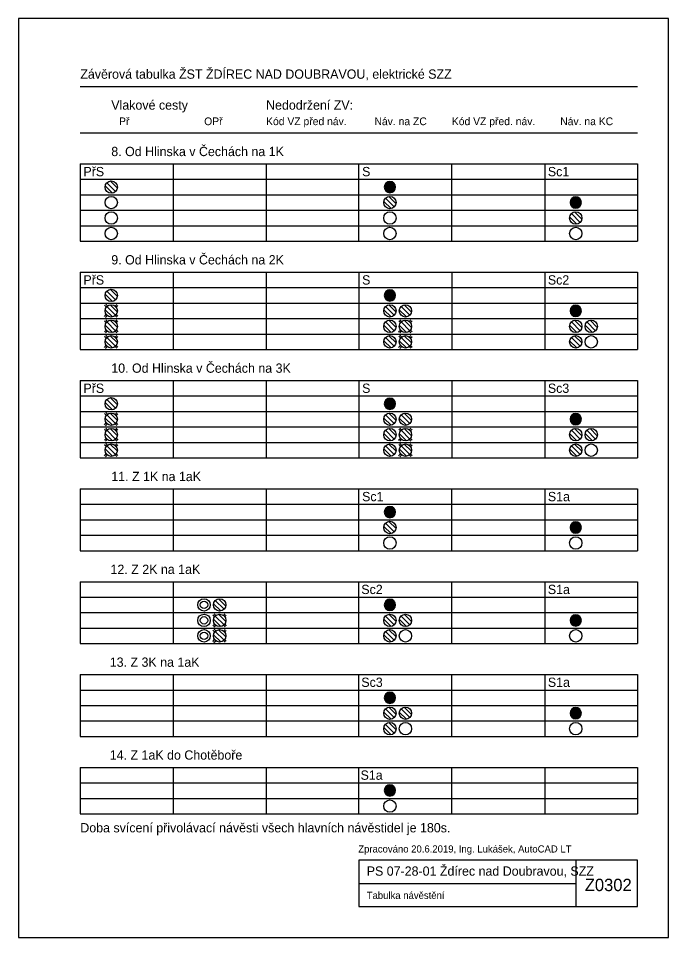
# Model space of a CAD drawing. Extents: x 2343 to 5155, y -3940 to 2050.
# Drawn here: x 4130 to 4340, y -3940 to -3643 of the extents above; entities that cross this region are included whole.
import ezdxf

# ---------------------------------------------------------------- set-up
doc = ezdxf.new("R2010")
doc.units = 0
for name, color, linetype in [('0B', 7, 'Continuous'), ('Implicitní', 7, 'Continuous'), ('Vrstva 63', 7, 'Continuous')]:
    doc.layers.add(name, color=color, linetype=linetype)

# ---------------------------------------------------------------- blocks, each defined once
blk = doc.blocks.new('ZT75')
at = {"layer": 'Implicitní'}
for points in [[(-18.1, 3.2), (18.1, 3.2)], [(-17.6, 0.7), (17.6, 0.7)], [(-17.3, 6.4), (17.3, 6.4)], [(-15.7, 9.6), (15.7, 9.6)], [(-14, 12), (14, 12)], [(-12.4, 13.6), (12.4, 13.6)], [(-10.4, 15.2), (10.4, 15.2)], [(-7.6, 16.8), (7.6, 16.8)], [(-18.1, -3.2), (18.1, -3.2)], [(-17.6, -0.7), (17.6, -0.7)], [(-17.3, -6.4), (17.3, -6.4)], [(-15.7, -9.6), (15.7, -9.6)], [(-14, -12), (14, -12)], [(-12.4, -13.6), (12.4, -13.6)], [(-10.4, -15.2), (10.4, -15.2)], [(-7.6, -16.8), (7.6, -16.8)]]:
    blk.add_lwpolyline(points, dxfattribs=at)
for start, end in [(0, 180), (180, 0)]:
    blk.add_arc((0, 0), 18.4, start, end, dxfattribs=at)
blk = doc.blocks.new('ZT76')
at = {"layer": 'Implicitní'}
for p, q in [((3.7, 19.7), (-19.7, -3.7)), ((14.1, 14.1), (-14.1, -14.1)), ((19.7, 3.7), (-3.7, -19.7))]:
    blk.add_line(p, q, dxfattribs=at)
blk.add_circle((0, 0), 20, dxfattribs=at)
blk = doc.blocks.new('ZT74')
at = {"layer": 'Implicitní'}
blk.add_circle((0, 0), 20, dxfattribs=at)
blk = doc.blocks.new('ZT78')
at = {"layer": 'Implicitní'}
for p, q in [((-30.7, 25.7), (-22.7, 17.7)), ((-25.7, 30.7), (-17.7, 22.7)), ((17.5, 21.7), (25.5, 29.7)), ((22.5, 16.7), (30.5, 24.7)), ((-31.3, -25.5), (-23.3, -17.5)), ((-26.3, -30.5), (-18.3, -22.5)), ((17.5, -21.7), (25.5, -29.7)), ((22.5, -16.7), (30.5, -24.7))]:
    blk.add_line(p, q, dxfattribs=at)
blk = doc.blocks.new('ZT72')
at = {"layer": 'Implicitní'}
for radius in [20, 12]:
    blk.add_circle((0, 0), radius, dxfattribs=at)

msp = doc.modelspace()

# ---------------------------------------------------------------- linework, layer by layer
at = {"layer": '0B'}
for p, q in [((4150, -3665), (4330, -3665)), ((4150, -3680), (4330, -3680)), ((4150, -3690), (4330, -3690)), ((4150, -3690), (4150, -3715)), ((4180, -3690), (4180, -3715)), ((4210, -3690), (4210, -3715)), ((4240, -3715), (4240, -3690)), ((4270, -3715), (4270, -3690)), ((4300, -3690), (4300, -3715)), ((4330, -3690), (4330, -3715)), ((4150, -3695), (4330, -3695)), ((4150, -3700), (4330, -3700)), ((4150, -3705), (4330, -3705)), ((4150, -3705), (4330, -3705)), ((4150, -3710), (4330, -3710)), ((4150, -3715), (4330, -3715)), ((4150, -3725), (4330, -3725)), ((4150, -3725), (4150, -3750)), ((4180, -3725), (4180, -3750)), ((4210, -3725), (4210, -3750)), ((4240, -3725), (4240, -3750)), ((4270, -3725), (4270, -3750)), ((4300, -3725), (4300, -3750)), ((4330, -3725), (4330, -3750)), ((4150, -3730), (4330, -3730)), ((4150, -3730), (4330, -3730)), ((4150, -3735), (4330, -3735)), ((4150, -3740), (4330, -3740)), ((4150, -3740), (4330, -3740)), ((4150, -3745), (4330, -3745)), ((4150, -3745), (4330, -3745)), ((4150, -3745), (4330, -3745)), ((4150, -3750), (4330, -3750)), ((4150, -3760), (4330, -3760)), ((4150, -3760), (4150, -3785)), ((4180, -3760), (4180, -3785)), ((4210, -3760), (4210, -3785)), ((4240, -3760), (4240, -3785)), ((4270, -3760), (4270, -3785)), ((4300, -3760), (4300, -3785)), ((4330, -3760), (4330, -3785)), ((4150, -3765), (4330, -3765)), ((4150, -3765), (4330, -3765)), ((4150, -3770), (4330, -3770)), ((4150, -3775), (4330, -3775)), ((4150, -3775), (4330, -3775)), ((4150, -3780), (4330, -3780)), ((4150, -3780), (4330, -3780)), ((4150, -3780), (4330, -3780)), ((4150, -3785), (4330, -3785)), ((4150, -3795), (4330, -3795)), ((4150, -3795), (4150, -3815)), ((4180, -3795), (4180, -3815)), ((4210, -3795), (4210, -3815)), ((4240, -3815), (4240, -3795)), ((4270, -3815), (4270, -3795)), ((4300, -3795), (4300, -3815)), ((4330, -3795), (4330, -3815)), ((4150, -3800), (4330, -3800)), ((4150, -3805), (4330, -3805)), ((4150, -3810), (4330, -3810)), ((4150, -3810), (4330, -3810)), ((4150, -3815), (4330, -3815)), ((4150, -3825), (4330, -3825)), ((4150, -3825), (4150, -3845)), ((4180, -3825), (4180, -3845)), ((4210, -3825), (4210, -3845)), ((4240, -3845), (4240, -3825)), ((4270, -3845), (4270, -3825)), ((4300, -3825), (4300, -3845)), ((4330, -3825), (4330, -3845)), ((4150, -3830), (4330, -3830)), ((4150, -3835), (4330, -3835)), ((4150, -3840), (4330, -3840)), ((4150, -3840), (4330, -3840)), ((4150, -3845), (4330, -3845)), ((4150, -3855), (4330, -3855)), ((4150, -3855), (4150, -3875)), ((4180, -3855), (4180, -3875)), ((4210, -3855), (4210, -3875)), ((4240, -3875), (4240, -3855)), ((4270, -3875), (4270, -3855)), ((4300, -3855), (4300, -3875)), ((4330, -3855), (4330, -3875)), ((4150, -3860), (4330, -3860)), ((4150, -3865), (4330, -3865)), ((4150, -3870), (4330, -3870)), ((4150, -3870), (4330, -3870)), ((4150, -3875), (4330, -3875)), ((4150, -3885), (4330, -3885)), ((4150, -3885), (4150, -3900)), ((4180, -3885), (4180, -3900)), ((4210, -3885), (4210, -3900)), ((4240, -3900), (4240, -3885)), ((4270, -3900), (4270, -3885)), ((4300, -3885), (4300, -3900)), ((4330, -3885), (4330, -3900)), ((4150, -3890), (4330, -3890)), ((4150, -3895), (4330, -3895)), ((4150, -3900), (4330, -3900)), ((4150, -3900), (4330, -3900)), ((4330, -3915), (4240, -3915)), ((4240, -3915), (4240, -3930)), ((4310, -3915), (4310, -3930)), ((4330, -3930), (4330, -3915)), ((4240, -3922.5), (4310, -3922.5)), ((4240, -3930), (4330, -3930))]:
    msp.add_line(p, q, dxfattribs=at)
at = {"layer": 'Vrstva 63'}
msp.add_lwpolyline([(4130, -3940), (4340, -3940), (4340, -3643), (4130, -3643)], close=True, dxfattribs=at)

# ---------------------------------------------------------------- block references
at = {"xscale": 0.1, "yscale": 0.10000000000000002}
for p in [(4189.95, -3832.5), (4189.95, -3837.5), (4189.95, -3842.5)]:
    msp.add_blockref('ZT72', p, dxfattribs=at)
at = {"layer": '0B'}
for name, p, xscale, yscale, rotation in [('ZT76', (4160, -3697.5), 0.10000000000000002, 0.1, 89.99999999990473), ('ZT75', (4250, -3697.5), 0.1, 0.10000000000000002, -9.526953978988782e-11), ('ZT74', (4160, -3702.5), 0.1, 0.10000000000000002, -9.526953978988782e-11), ('ZT76', (4250, -3702.5), 0.10000000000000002, 0.1, 89.99999999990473), ('ZT75', (4310, -3702.5), 0.1, 0.10000000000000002, -9.526953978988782e-11), ('ZT74', (4160, -3707.5), 0.1, 0.10000000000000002, -9.526953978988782e-11), ('ZT74', (4250, -3707.5), 0.1, 0.10000000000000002, -9.526953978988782e-11), ('ZT76', (4310, -3707.5), 0.10000000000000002, 0.10000000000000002, 89.99999999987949), ('ZT74', (4160, -3712.5), 0.1, 0.10000000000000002, -9.526953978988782e-11), ('ZT74', (4250, -3712.5), 0.1, 0.10000000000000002, -9.526953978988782e-11), ('ZT74', (4310, -3712.5), 0.1, 0.10000000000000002, -9.526953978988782e-11), ('ZT76', (4160, -3732.5), 0.10000000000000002, 0.10000000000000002, 89.99999999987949), ('ZT75', (4250, -3732.5), 0.1, 0.10000000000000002, -1.2050326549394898e-10), ('ZT78', (4160, -3737.5), 0.06999999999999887, 0.06999999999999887, -1.2050326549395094e-10), ('ZT76', (4160, -3737.5), 0.10000000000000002, 0.10000000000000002, 89.99999999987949), ('ZT76', (4250, -3737.5), 0.10000000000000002, 0.10000000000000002, 89.99999999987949), ('ZT76', (4255, -3737.5), 0.10000000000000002, 0.10000000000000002, 89.99999999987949), ('ZT76', (4255, -3737.5), 0.10000000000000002, 0.10000000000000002, 89.99999999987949), ('ZT75', (4310, -3737.5), 0.1, 0.10000000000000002, -1.2050326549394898e-10), ('ZT78', (4160, -3742.5), 0.06999999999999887, 0.06999999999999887, -1.2050326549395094e-10), ('ZT76', (4160, -3742.5), 0.10000000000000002, 0.10000000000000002, 89.99999999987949), ('ZT76', (4250, -3742.5), 0.10000000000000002, 0.10000000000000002, 89.99999999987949), ('ZT78', (4255, -3742.5), 0.06999999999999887, 0.06999999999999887, -1.2050326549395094e-10), ('ZT76', (4255, -3742.5), 0.10000000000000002, 0.10000000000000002, 89.99999999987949), ('ZT76', (4255, -3742.5), 0.10000000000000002, 0.10000000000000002, 89.99999999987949), ('ZT76', (4310, -3742.5), 0.10000000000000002, 0.10000000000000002, 89.99999999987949), ('ZT76', (4315, -3742.5), 0.10000000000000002, 0.10000000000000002, 89.99999999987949), ('ZT78', (4160, -3747.5), 0.06999999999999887, 0.06999999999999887, -1.2050326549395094e-10), ('ZT76', (4160, -3747.5), 0.10000000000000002, 0.10000000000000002, 89.99999999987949), ('ZT76', (4250, -3747.5), 0.10000000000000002, 0.10000000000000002, 89.99999999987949), ('ZT78', (4255, -3747.5), 0.06999999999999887, 0.06999999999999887, -1.2050326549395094e-10), ('ZT76', (4255, -3747.5), 0.10000000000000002, 0.10000000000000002, 89.99999999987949), ('ZT76', (4255, -3747.5), 0.10000000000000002, 0.10000000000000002, 89.99999999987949), ('ZT76', (4310, -3747.5), 0.10000000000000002, 0.10000000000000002, 89.99999999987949), ('ZT74', (4315, -3747.5), 0.1, 0.10000000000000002, -1.2050326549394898e-10), ('ZT76', (4160, -3767.5), 0.10000000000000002, 0.10000000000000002, 89.99999999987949), ('ZT75', (4250, -3767.5), 0.1, 0.10000000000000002, -1.2050326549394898e-10), ('ZT78', (4160, -3772.5), 0.06999999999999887, 0.06999999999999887, -1.2050326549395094e-10), ('ZT76', (4160, -3772.5), 0.10000000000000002, 0.10000000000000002, 89.99999999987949), ('ZT76', (4250, -3772.5), 0.10000000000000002, 0.10000000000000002, 89.99999999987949), ('ZT76', (4255, -3772.5), 0.10000000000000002, 0.10000000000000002, 89.99999999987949), ('ZT76', (4255, -3772.5), 0.10000000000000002, 0.10000000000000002, 89.99999999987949), ('ZT75', (4310, -3772.5), 0.1, 0.10000000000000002, -1.2050326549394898e-10), ('ZT78', (4160, -3777.5), 0.06999999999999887, 0.06999999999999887, -1.2050326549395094e-10), ('ZT76', (4160, -3777.5), 0.10000000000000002, 0.10000000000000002, 89.99999999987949), ('ZT76', (4250, -3777.5), 0.10000000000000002, 0.10000000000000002, 89.99999999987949), ('ZT78', (4255, -3777.5), 0.06999999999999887, 0.06999999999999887, -1.2050326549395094e-10), ('ZT76', (4255, -3777.5), 0.10000000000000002, 0.10000000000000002, 89.99999999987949), ('ZT76', (4255, -3777.5), 0.10000000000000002, 0.10000000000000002, 89.99999999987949), ('ZT76', (4310, -3777.5), 0.10000000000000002, 0.10000000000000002, 89.99999999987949), ('ZT76', (4315, -3777.5), 0.10000000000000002, 0.10000000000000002, 89.99999999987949), ('ZT78', (4160, -3782.5), 0.06999999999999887, 0.06999999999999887, -1.2050326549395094e-10), ('ZT76', (4160, -3782.5), 0.10000000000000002, 0.10000000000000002, 89.99999999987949), ('ZT76', (4250, -3782.5), 0.10000000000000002, 0.10000000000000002, 89.99999999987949), ('ZT78', (4255, -3782.5), 0.06999999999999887, 0.06999999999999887, -1.2050326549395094e-10), ('ZT76', (4255, -3782.5), 0.10000000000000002, 0.10000000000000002, 89.99999999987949), ('ZT76', (4255, -3782.5), 0.10000000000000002, 0.10000000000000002, 89.99999999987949), ('ZT76', (4310, -3782.5), 0.10000000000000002, 0.10000000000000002, 89.99999999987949), ('ZT74', (4315, -3782.5), 0.1, 0.10000000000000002, -1.2050326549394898e-10), ('ZT75', (4250, -3802.5), 0.1, 0.10000000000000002, -1.2050326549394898e-10), ('ZT76', (4250, -3807.5), 0.10000000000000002, 0.10000000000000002, 89.99999999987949), ('ZT75', (4310, -3807.5), 0.1, 0.10000000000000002, -9.526953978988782e-11), ('ZT74', (4250, -3812.5), 0.1, 0.10000000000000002, -1.2050326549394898e-10), ('ZT74', (4310, -3812.5), 0.1, 0.10000000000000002, -9.526953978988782e-11), ('ZT76', (4195, -3832.5), 0.10000000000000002, 0.10000000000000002, 89.99999999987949), ('ZT75', (4250, -3832.5), 0.1, 0.10000000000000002, -1.2050326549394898e-10), ('ZT78', (4195, -3837.5), 0.06999999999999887, 0.06999999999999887, -1.2050326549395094e-10), ('ZT76', (4195, -3837.5), 0.10000000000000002, 0.10000000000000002, 89.99999999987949), ('ZT76', (4250, -3837.5), 0.10000000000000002, 0.10000000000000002, 89.99999999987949), ('ZT76', (4255, -3837.5), 0.10000000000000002, 0.10000000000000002, 89.99999999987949), ('ZT75', (4310, -3837.5), 0.1, 0.10000000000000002, -9.526953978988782e-11), ('ZT78', (4195, -3842.5), 0.06999999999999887, 0.06999999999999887, -1.2050326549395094e-10), ('ZT76', (4195, -3842.5), 0.10000000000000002, 0.10000000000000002, 89.99999999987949), ('ZT76', (4250, -3842.5), 0.10000000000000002, 0.10000000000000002, 89.99999999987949), ('ZT74', (4255, -3842.5), 0.1, 0.10000000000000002, -1.2050326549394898e-10), ('ZT74', (4310, -3842.5), 0.1, 0.10000000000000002, -9.526953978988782e-11), ('ZT75', (4250, -3862.5), 0.1, 0.10000000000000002, -1.2050326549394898e-10), ('ZT76', (4250, -3867.5), 0.10000000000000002, 0.10000000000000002, 89.99999999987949), ('ZT76', (4255, -3867.5), 0.10000000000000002, 0.10000000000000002, 89.99999999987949), ('ZT75', (4310, -3867.5), 0.1, 0.10000000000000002, -9.526953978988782e-11), ('ZT76', (4250, -3872.5), 0.10000000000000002, 0.10000000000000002, 89.99999999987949), ('ZT74', (4255, -3872.5), 0.1, 0.10000000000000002, -1.2050326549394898e-10), ('ZT74', (4310, -3872.5), 0.1, 0.10000000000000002, -9.526953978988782e-11), ('ZT75', (4250, -3892.43), 0.1, 0.10000000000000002, -1.2050326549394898e-10), ('ZT74', (4250, -3897.5), 0.1, 0.10000000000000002, -1.2050326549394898e-10)]:
    msp.add_blockref(name, p, dxfattribs=dict(at, xscale=xscale, yscale=yscale, rotation=rotation))

# ---------------------------------------------------------------- texts
for s, height, p in [('Závěrová tabulka ŽST ŽDÍREC NAD DOUBRAVOU, elektrické SZZ', 3, (4150, -3662.5)), ('Vlakové cesty', 3, (4160, -3672.5)), ('Nedodržení ZV:', 3, (4210, -3672.5)), ('Př', 2.5, (4162.5, -3677.5)), ('OPř', 2.5, (4190, -3677.5)), ('Kód VZ před náv.', 2.5, (4210, -3677.5)), ('Náv. na ZC', 2.5, (4245, -3677.5)), ('Kód VZ před. náv.', 2.5, (4270, -3677.5)), ('Náv. na KC', 2.5, (4305, -3677.5)), ('8. Od Hlinska v Čechách na 1K', 3, (4160, -3687.5)), ('PřS', 3, (4151, -3694)), ('S', 3, (4241, -3694)), ('Sc1', 3, (4301, -3694)), ('9. Od Hlinska v Čechách na 2K', 3, (4160, -3722.5)), ('PřS', 3, (4151, -3729)), ('S', 3, (4241, -3729)), ('Sc2', 3, (4301, -3729)), ('10. Od Hlinska v Čechách na 3K', 3, (4160, -3757.5)), ('PřS', 3, (4151, -3764)), ('S', 3, (4241, -3764)), ('Sc3', 3, (4301, -3764)), ('11. Z 1K na 1aK', 3, (4160, -3792.5)), ('Sc1', 3, (4241, -3799)), ('S1a', 3, (4301, -3799)), ('12. Z 2K na 1aK', 3, (4159.75, -3822.5)), ('Sc2', 3, (4240.75, -3829)), ('S1a', 3, (4301, -3829)), ('13. Z 3K na 1aK', 3, (4159.51, -3852.5)), ('Sc3', 3, (4240.75, -3859)), ('S1a', 3, (4301, -3859)), ('14. Z 1aK do Chotěboře', 3, (4159.51, -3882.5)), ('S1a', 3, (4240.51, -3889)), ('Doba svícení přivolávací návěsti všech hlavních návěstidel je 180s.', 3, (4150, -3906)), ('Zpracováno 20.6.2019, Ing. Lukášek, AutoCAD LT', 2.2988, (4239.77, -3912.5)), ('PS 07-28-01 Ždírec nad Doubravou, SZZ', 3, (4242.5, -3920)), ('Z0302', 4, (4312.92, -3924.98)), ('Tabulka návěstění', 2.3, (4242.5, -3927.5))]:
    msp.add_text(s, height=height, rotation=360, dxfattribs=at).set_placement(p)

doc.saveas('drawing.dxf')
